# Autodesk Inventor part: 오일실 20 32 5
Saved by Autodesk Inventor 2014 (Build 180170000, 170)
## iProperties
Created: 2024-08
Part Number: 오일실 20 32 5
Material: 일반
Document SubType Name: Modeling
Designer: dg
Density: 1 g/cm^3
Appearance: 기본값
Author: dg
Author: jhkim
Description: 오일 실 - 비스프링, 조립 GA
Creation Date: 2024-08-09
Sending System: Autodesk Inventor 2025
Preprocessor: ST-DEVELOPER v20
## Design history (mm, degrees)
node "오일실 20 32 51"
body "Solid1"
node "기준1"
